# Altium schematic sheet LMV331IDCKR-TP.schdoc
size 127 x 101 mm
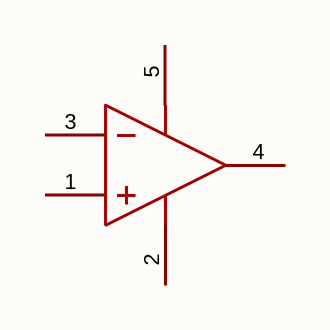
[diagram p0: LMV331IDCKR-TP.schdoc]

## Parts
U?  lmv331idckr-tp  [SOT-353-5_L2.0-W1.3-P0.65-LS2.1-BL]  (value not drawn)

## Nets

Not connected (* = marked no-connect by the designer): U? 1(IN+) 2(V-) 3(IN-) 4(OUT) 5(V+)

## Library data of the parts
U? = lmv331idckr-tp: 输入失调电压(Vos):800uV;输入偏置电流(Ib):2pA;; Manufacturer: TECH PUBLIC(台舟); AddInBom: yes; ModelId: 53104ecfa15f4942b2fe744c119b4961; ModelTransform: 78.74,82.677,0,0,0,0,0,0,0; Vos - Input Offset Voltage: 800uV; Ib - Input Bias Current: 2pA; Propagation Delay Time: 950ns；460ns; Output Type: 开漏; Quiescent Current: 29uA；50uA; Maximum Power Supply Range (Vdd-Vss): 7V; Single Supply: 1.8V~5.5V; Input Offset Voltage Drift(Vos TC): 0.8uV/℃; Input Offset Current(Ios): 1pA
